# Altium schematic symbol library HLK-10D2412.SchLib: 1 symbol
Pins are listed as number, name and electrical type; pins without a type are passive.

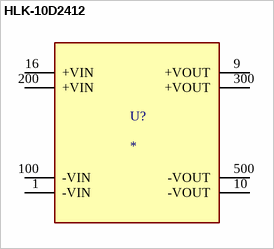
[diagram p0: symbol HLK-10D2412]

## HLK-10D2412
designator U?
Isolated Module DC DC Converter Input: 9-24V   output: +12; MP: A1205S-2W; MF: Traco Power
footprint HLK-10D2412
pins: 1 -VIN (power), 9 +VOUT, 10 -VOUT (power), 16 +VIN (power), 100 -VIN (power), 200 +VIN (power), 300 +VOUT, 500 -VOUT (power)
